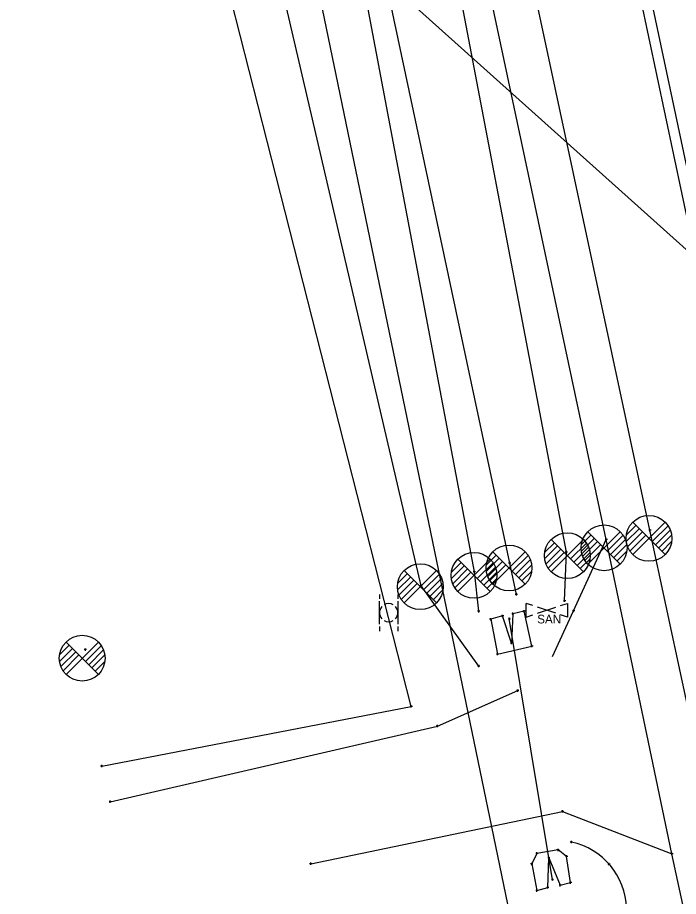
# Model space of a CAD drawing. Extents: x 1954856 to 2011933, y 399149 to 426294.
# Drawn here: x 2005971.8 to 2006043.9, y 402947.5 to 403043.4 of the extents above; entities that cross this region are included whole.
import ezdxf

# ---------------------------------------------------------------- set-up
doc = ezdxf.new("R2010")
doc.units = 0
for name, color, linetype in [('BankMent_ep', 7, 'Continuous'), ('BaselineSurvey', 7, 'Continuous'), ('DelineatorPost_ep', 7, 'Continuous'), ('Driveway_ep', 7, 'Continuous'), ('ElecAer_ep', 7, 'Continuous'), ('EndTreatMES_ep', 7, 'Continuous'), ('FlowLineInvert_ep', 7, 'Continuous'), ('PavtAsphalt_ep', 7, 'Continuous'), ('PavtAsphaltCrown_ep', 7, 'Continuous'), ('PipeCulvert_ep', 7, 'Continuous'), ('PointLocator_ep', 7, 'Continuous'), ('ShldrPaved_ep', 7, 'Continuous'), ('TreeLineWoods_ep', 7, 'Continuous'), ('ValveSewer_ep', 7, 'Continuous'), ('XSPt_ep', 7, 'Continuous')]:
    doc.layers.add(name, color=color, linetype=linetype)

msp = doc.modelspace()

# ---------------------------------------------------------------- linework, layer by layer
at = {"layer": 'BankMent_ep'}
for p, q in [((2006031.644, 402985.086), (2006013.054, 403082.745)), ((2006015.787, 402981.415), (2005993.355, 403077.812)), ((2006031.445, 402979.774), (2006031.644, 402985.086)), ((2006022.071, 402972.641), (2006015.787, 402981.415))]:
    msp.add_line(p, q, dxfattribs=at)
for points in [[(2006026.182, 402980.462), (2006025.451, 402983.887), (2006004.796, 403080.94), (2005986.553, 403176.869), (2005964.789, 403276.966), (2005944.375, 403374.63), (2005923.277, 403472.991), (2005901.17, 403570.474), (2005889.775, 403641.659)], [(2006022.07, 402978.635), (2006021.603, 402982.934), (2006003.186, 403080.575), (2005983.54, 403176.275), (2005962.468, 403276.293), (2005940.441, 403373.603), (2005921.465, 403472.813), (2005899.513, 403569.733), (2005886.484, 403640.977)]]:
    msp.add_lwpolyline(points, dxfattribs=at)
msp.add_arc((2006030.56, 402945.974), 7.645, 1.8807, 77.76145, dxfattribs=at)
at = {"layer": 'BaselineSurvey'}
msp.add_line((2006223.925, 402174.382), (2005094.479, 407516.047), dxfattribs=at)
msp.add_line((2006223.925, 402174.382), (2005094.479, 407516.047), dxfattribs=at)
at = {"layer": 'DelineatorPost_ep'}
for p, q in [((2006011.243, 402980.474), (2006011.243, 402979.974)), ((2006011.243, 402977.224), (2006011.243, 402979.724)), ((2006013.243, 402980.474), (2006013.243, 402979.974)), ((2006013.243, 402979.724), (2006013.243, 402977.224)), ((2006012.243, 402978.474), (2006012.243, 402978.474)), ((2006011.243, 402976.974), (2006011.243, 402976.474)), ((2006013.243, 402976.974), (2006013.243, 402976.474))]:
    msp.add_line(p, q, dxfattribs=at)
for start, end in [(138.59038, 221.40962), (60, 120), (318.59038, 41.40962), (240, 300)]:
    msp.add_arc((2006012.243, 402978.474), 1, start, end, dxfattribs=at)
at = {"layer": 'Driveway_ep'}
for p, q in [((2006032.413, 402978.669), (2006035.99, 402986.452)), ((2006030.134, 402973.71), (2006032.413, 402978.669)), ((2006017.562, 402966.093), (2006026.332, 402969.965)), ((2005981.873, 402957.848), (2006017.562, 402966.093)), ((2006003.74, 402951.077), (2006031.217, 402956.789)), ((2006031.217, 402956.789), (2006043.151, 402952.168))]:
    msp.add_line(p, q, dxfattribs=at)
at = {"layer": 'ElecAer_ep'}
msp.add_lwpolyline([(2006062.406, 402767.04), (2006002.661, 403055.822), (2006083.898, 402982.967)], dxfattribs=at)
at = {"layer": 'EndTreatMES_ep'}
for points in [[(2006023.384, 402977.75), (2006024.136, 402973.955), (2006027.869, 402974.829), (2006027.017, 402978.629), (2006025.793, 402978.353), (2006025.649, 402975.151), (2006024.679, 402978.115)], [(2006032.09, 402949.017), (2006031.659, 402951.872), (2006030.733, 402952.588), (2006028.412, 402952.204), (2006027.849, 402951.057), (2006028.409, 402948.141), (2006029.611, 402948.486), (2006029.717, 402951.726), (2006030.954, 402948.729)]]:
    msp.add_lwpolyline(points, close=True, dxfattribs=at)
at = {"layer": 'FlowLineInvert_ep'}
for p, q in [((2006025.494, 402977.744), (2006025.318, 402977.92)), ((2006025.494, 402977.92), (2006025.318, 402977.744)), ((2006025.406, 402977.832), (2006025.406, 402977.832)), ((2006030.209, 402949.239), (2006030.033, 402949.415)), ((2006030.209, 402949.415), (2006030.033, 402949.239)), ((2006030.121, 402949.327), (2006030.121, 402949.327))]:
    msp.add_line(p, q, dxfattribs=at)
at = {"layer": 'PavtAsphalt_ep'}
for p, q in [((2006040.75, 402987.463), (2006019.985, 403084.459)), ((2006061.812, 402888.943), (2006040.75, 402987.463))]:
    msp.add_line(p, q, dxfattribs=at)
at = {"layer": 'PavtAsphaltCrown_ep'}
msp.add_lwpolyline([(2006221.576, 402197.041), (2006219.373, 402206.688), (2006198.419, 402304.427), (2006177.674, 402402.212), (2006156.488, 402500.143), (2006135.917, 402597.882), (2006115.394, 402695.489), (2006094.3, 402793.442), (2006073.801, 402891.433), (2006052.859, 402989.16), (2006032.075, 403086.962), (2006011.062, 403184.663), (2005990.583, 403282.628), (2005969.857, 403380.234), (2005949.302, 403478.326), (2005928.678, 403576.103), (2005908.104, 403674.029), (2005887.142, 403771.84)], dxfattribs=at)
at = {"layer": 'PipeCulvert_ep'}
msp.add_lwpolyline([(2006030.121, 402949.327), (2006025.406, 402977.832)], dxfattribs=at)
at = {"layer": 'PointLocator_ep'}
for p, q in [((2006040.875, 402987.463), (2006040.625, 402987.463)), ((2006040.75, 402987.338), (2006040.75, 402987.588)), ((2006040.75, 402987.463), (2006040.75, 402987.463)), ((2006036.115, 402986.452), (2006035.865, 402986.452)), ((2006035.99, 402986.327), (2006035.99, 402986.577)), ((2006035.99, 402986.452), (2006035.99, 402986.452)), ((2006031.769, 402985.086), (2006031.519, 402985.086)), ((2006031.644, 402984.961), (2006031.644, 402985.211)), ((2006031.644, 402985.086), (2006031.644, 402985.086)), ((2006025.576, 402983.887), (2006025.326, 402983.887)), ((2006025.451, 402983.762), (2006025.451, 402984.012)), ((2006025.451, 402983.887), (2006025.451, 402983.887)), ((2006021.728, 402982.934), (2006021.478, 402982.934)), ((2006021.603, 402982.809), (2006021.603, 402983.059)), ((2006021.603, 402982.934), (2006021.603, 402982.934)), ((2006015.787, 402981.29), (2006015.787, 402981.54)), ((2006015.912, 402981.415), (2006015.662, 402981.415)), ((2006015.787, 402981.415), (2006015.787, 402981.415)), ((2006026.182, 402980.337), (2006026.182, 402980.587)), ((2006026.307, 402980.462), (2006026.057, 402980.462)), ((2006026.182, 402980.462), (2006026.182, 402980.462)), ((2006031.57, 402979.774), (2006031.32, 402979.774)), ((2006031.445, 402979.649), (2006031.445, 402979.899)), ((2006031.445, 402979.774), (2006031.445, 402979.774)), ((2006022.07, 402978.51), (2006022.07, 402978.76)), ((2006027.017, 402978.504), (2006027.017, 402978.754)), ((2006032.538, 402978.669), (2006032.288, 402978.669)), ((2006032.413, 402978.544), (2006032.413, 402978.794)), ((2006032.413, 402978.669), (2006032.413, 402978.669)), ((2006022.195, 402978.635), (2006021.945, 402978.635)), ((2006022.07, 402978.635), (2006022.07, 402978.635)), ((2006023.509, 402977.75), (2006023.259, 402977.75)), ((2006023.384, 402977.625), (2006023.384, 402977.875)), ((2006023.384, 402977.75), (2006023.384, 402977.75)), ((2006024.804, 402978.115), (2006024.554, 402978.115)), ((2006024.679, 402977.99), (2006024.679, 402978.24)), ((2006024.679, 402978.115), (2006024.679, 402978.115)), ((2006025.918, 402978.353), (2006025.668, 402978.353)), ((2006025.793, 402978.228), (2006025.793, 402978.478)), ((2006025.793, 402978.353), (2006025.793, 402978.353)), ((2006027.142, 402978.629), (2006026.892, 402978.629)), ((2006027.017, 402978.629), (2006027.017, 402978.629)), ((2006025.774, 402975.151), (2006025.524, 402975.151)), ((2006025.649, 402975.026), (2006025.649, 402975.276)), ((2006025.649, 402975.151), (2006025.649, 402975.151)), ((2006027.994, 402974.829), (2006027.744, 402974.829)), ((2006027.869, 402974.704), (2006027.869, 402974.954)), ((2006027.869, 402974.829), (2006027.869, 402974.829)), ((2005979.279, 402974.448), (2005979.029, 402974.448)), ((2005979.154, 402974.323), (2005979.154, 402974.573)), ((2005979.154, 402974.448), (2005979.154, 402974.448)), ((2006024.261, 402973.955), (2006024.011, 402973.955)), ((2006024.136, 402973.83), (2006024.136, 402974.08)), ((2006024.136, 402973.955), (2006024.136, 402973.955)), ((2006022.196, 402972.641), (2006021.946, 402972.641)), ((2006022.071, 402972.516), (2006022.071, 402972.766)), ((2006022.071, 402972.641), (2006022.071, 402972.641)), ((2006026.332, 402969.84), (2006026.332, 402970.09)), ((2006026.457, 402969.965), (2006026.207, 402969.965)), ((2006026.332, 402969.965), (2006026.332, 402969.965)), ((2006014.835, 402968.248), (2006014.585, 402968.248)), ((2006014.71, 402968.123), (2006014.71, 402968.373)), ((2006014.71, 402968.248), (2006014.71, 402968.248)), ((2006017.562, 402965.968), (2006017.562, 402966.218)), ((2006017.687, 402966.093), (2006017.437, 402966.093)), ((2006017.562, 402966.093), (2006017.562, 402966.093)), ((2005981.059, 402961.73), (2005980.809, 402961.73)), ((2005980.934, 402961.605), (2005980.934, 402961.855)), ((2005980.934, 402961.73), (2005980.934, 402961.73)), ((2005981.998, 402957.848), (2005981.748, 402957.848)), ((2005981.873, 402957.723), (2005981.873, 402957.973)), ((2005981.873, 402957.848), (2005981.873, 402957.848)), ((2006031.342, 402956.789), (2006031.092, 402956.789)), ((2006031.217, 402956.664), (2006031.217, 402956.914)), ((2006031.217, 402956.789), (2006031.217, 402956.789)), ((2006032.306, 402953.445), (2006032.056, 402953.445)), ((2006032.181, 402953.32), (2006032.181, 402953.57)), ((2006032.181, 402953.445), (2006032.181, 402953.445)), ((2006028.537, 402952.204), (2006028.287, 402952.204)), ((2006028.412, 402952.079), (2006028.412, 402952.329)), ((2006028.412, 402952.204), (2006028.412, 402952.204)), ((2006029.717, 402951.601), (2006029.717, 402951.851)), ((2006030.858, 402952.588), (2006030.608, 402952.588)), ((2006030.733, 402952.463), (2006030.733, 402952.713)), ((2006030.733, 402952.588), (2006030.733, 402952.588)), ((2006031.784, 402951.872), (2006031.534, 402951.872)), ((2006031.659, 402951.747), (2006031.659, 402951.997)), ((2006031.659, 402951.872), (2006031.659, 402951.872)), ((2006043.276, 402952.168), (2006043.026, 402952.168)), ((2006043.151, 402952.043), (2006043.151, 402952.293)), ((2006043.151, 402952.168), (2006043.151, 402952.168)), ((2006003.865, 402951.077), (2006003.615, 402951.077)), ((2006003.74, 402950.952), (2006003.74, 402951.202)), ((2006003.74, 402951.077), (2006003.74, 402951.077)), ((2006027.974, 402951.057), (2006027.724, 402951.057)), ((2006027.849, 402950.932), (2006027.849, 402951.182)), ((2006027.849, 402951.057), (2006027.849, 402951.057)), ((2006029.842, 402951.726), (2006029.592, 402951.726)), ((2006029.717, 402951.726), (2006029.717, 402951.726)), ((2006036.408, 402951.043), (2006036.158, 402951.043)), ((2006036.283, 402950.918), (2006036.283, 402951.168)), ((2006036.283, 402951.043), (2006036.283, 402951.043)), ((2006032.215, 402949.017), (2006031.965, 402949.017)), ((2006032.09, 402948.892), (2006032.09, 402949.142)), ((2006032.09, 402949.017), (2006032.09, 402949.017)), ((2006028.534, 402948.141), (2006028.284, 402948.141)), ((2006028.409, 402948.016), (2006028.409, 402948.266)), ((2006028.409, 402948.141), (2006028.409, 402948.141)), ((2006029.736, 402948.486), (2006029.486, 402948.486)), ((2006029.611, 402948.361), (2006029.611, 402948.611)), ((2006029.611, 402948.486), (2006029.611, 402948.486)), ((2006031.079, 402948.729), (2006030.829, 402948.729)), ((2006030.954, 402948.604), (2006030.954, 402948.854)), ((2006030.954, 402948.729), (2006030.954, 402948.729))]:
    msp.add_line(p, q, dxfattribs=at)
at = {"layer": 'ShldrPaved_ep'}
for p, q in [((2006035.99, 402986.452), (2006015.245, 403083.769)), ((2006043.151, 402952.168), (2006035.99, 402986.452)), ((2006057.174, 402887.717), (2006043.151, 402952.168))]:
    msp.add_line(p, q, dxfattribs=at)
at = {"layer": 'TreeLineWoods_ep'}
msp.add_lwpolyline([(2005980.934, 402961.73), (2006014.71, 402968.248), (2005987.203, 403076.245), (2005968.268, 403172.205), (2005947.454, 403273.053), (2005926.011, 403370.82), (2005905.04, 403469.001), (2005886.708, 403566.956), (2005868.55, 403644.14), (2005837.958, 403637.86)], dxfattribs=at)
at = {"layer": 'ValveSewer_ep'}
for p, q in [((2006027.99, 402979.244), (2006027.24, 402979.494)), ((2006027.24, 402977.994), (2006027.24, 402979.494)), ((2006030.49, 402978.411), (2006028.49, 402979.077)), ((2006028.49, 402978.411), (2006030.49, 402979.077)), ((2006029.49, 402978.744), (2006029.49, 402978.744)), ((2006030.99, 402979.244), (2006031.74, 402979.494)), ((2006031.74, 402979.494), (2006031.74, 402977.994)), ((2006027.24, 402977.994), (2006027.99, 402978.244)), ((2006031.74, 402977.994), (2006030.99, 402978.244))]:
    msp.add_line(p, q, dxfattribs=at)
at = {"layer": 'XSPt_ep'}
for p, q in [((2006038.871, 402984.813), (2006042.407, 402988.349)), ((2006042.407, 402984.813), (2006038.871, 402988.349)), ((2006033.98, 402983.779), (2006037.516, 402987.315)), ((2006037.516, 402983.779), (2006033.98, 402987.315)), ((2006038.164, 402986.935), (2006039.225, 402987.995)), ((2006038.164, 402986.227), (2006039.578, 402987.642)), ((2006038.312, 402985.668), (2006039.932, 402987.288)), ((2006040.993, 402986.227), (2006042.725, 402987.959)), ((2006041.346, 402985.874), (2006042.966, 402987.494)), ((2006029.968, 402982.93), (2006033.504, 402986.466)), ((2006033.504, 402982.93), (2006029.968, 402986.466)), ((2006033.273, 402985.901), (2006034.334, 402986.961)), ((2006033.273, 402985.193), (2006034.687, 402986.608)), ((2006036.102, 402985.193), (2006037.834, 402986.925)), ((2006036.455, 402984.84), (2006038.075, 402986.46)), ((2006038.553, 402985.203), (2006040.285, 402986.935)), ((2006040.639, 402986.581), (2006040.639, 402986.581)), ((2006041.7, 402985.52), (2006043.114, 402986.935)), ((2006029.261, 402985.052), (2006030.322, 402986.112)), ((2006029.261, 402984.344), (2006030.675, 402985.759)), ((2006029.409, 402983.785), (2006031.029, 402985.405)), ((2006032.09, 402984.344), (2006033.822, 402986.076)), ((2006032.443, 402983.991), (2006034.063, 402985.611)), ((2006033.421, 402984.634), (2006035.041, 402986.254)), ((2006033.662, 402984.169), (2006035.394, 402985.901)), ((2006035.748, 402985.547), (2006035.748, 402985.547)), ((2006036.809, 402984.486), (2006038.223, 402985.901)), ((2006042.053, 402985.167), (2006043.114, 402986.227)), ((2006022.902, 402983.708), (2006023.963, 402984.768)), ((2006022.902, 402983), (2006024.316, 402984.415)), ((2006023.609, 402981.586), (2006027.145, 402985.122)), ((2006027.145, 402981.586), (2006023.609, 402985.122)), ((2006025.731, 402983), (2006027.463, 402984.732)), ((2006029.65, 402983.32), (2006031.382, 402985.052)), ((2006031.736, 402984.698), (2006031.736, 402984.698)), ((2006032.797, 402983.637), (2006034.211, 402985.052)), ((2006037.162, 402984.133), (2006038.223, 402985.193)), ((2006019.086, 402982.901), (2006020.147, 402983.961)), ((2006019.086, 402982.193), (2006020.5, 402983.608)), ((2006019.793, 402980.779), (2006023.329, 402984.315)), ((2006023.329, 402980.779), (2006019.793, 402984.315)), ((2006021.915, 402982.193), (2006023.647, 402983.925)), ((2006022.268, 402981.84), (2006023.888, 402983.46)), ((2006023.05, 402982.441), (2006024.67, 402984.061)), ((2006023.291, 402981.976), (2006025.023, 402983.708)), ((2006026.084, 402982.647), (2006027.704, 402984.267)), ((2006026.438, 402982.293), (2006027.852, 402983.708)), ((2006033.15, 402983.284), (2006034.211, 402984.344)), ((2006013.216, 402981.66), (2006014.277, 402982.72)), ((2006013.923, 402979.538), (2006017.459, 402983.074)), ((2006017.459, 402979.538), (2006013.923, 402983.074)), ((2006016.045, 402980.952), (2006017.777, 402982.684)), ((2006019.234, 402981.634), (2006020.854, 402983.254)), ((2006019.475, 402981.169), (2006021.207, 402982.901)), ((2006021.561, 402982.547), (2006021.561, 402982.547)), ((2006022.622, 402981.486), (2006024.036, 402982.901)), ((2006025.377, 402983.354), (2006025.377, 402983.354)), ((2006026.791, 402981.94), (2006027.852, 402983)), ((2006013.216, 402980.952), (2006014.63, 402982.367)), ((2006013.364, 402980.393), (2006014.984, 402982.013)), ((2006013.605, 402979.928), (2006015.337, 402981.66)), ((2006016.398, 402980.599), (2006018.018, 402982.219)), ((2006016.752, 402980.245), (2006018.166, 402981.66)), ((2006022.975, 402981.133), (2006024.036, 402982.193)), ((2006015.691, 402981.306), (2006015.691, 402981.306)), ((2006017.105, 402979.892), (2006018.166, 402980.952)), ((2005976.332, 402973.861), (2005977.393, 402974.921)), ((2005977.039, 402971.739), (2005980.575, 402975.275)), ((2005980.575, 402971.739), (2005977.039, 402975.275)), ((2005979.161, 402973.153), (2005980.893, 402974.885)), ((2005976.332, 402973.153), (2005977.746, 402974.568)), ((2005976.48, 402972.594), (2005978.1, 402974.214)), ((2005976.721, 402972.129), (2005978.453, 402973.861)), ((2005979.514, 402972.8), (2005981.134, 402974.42)), ((2005979.868, 402972.446), (2005981.282, 402973.861)), ((2005978.807, 402973.507), (2005978.807, 402973.507)), ((2005980.221, 402972.093), (2005981.282, 402973.153))]:
    msp.add_line(p, q, dxfattribs=at)
for centre in [(2006040.639, 402986.581), (2006035.748, 402985.547), (2006031.736, 402984.698), (2006025.377, 402983.354), (2006021.561, 402982.547), (2006015.691, 402981.306), (2005978.807, 402973.507)]:
    msp.add_circle(centre, 2.5, dxfattribs=at)

# ---------------------------------------------------------------- texts
at = {"layer": 'ValveSewer_ep'}
msp.add_text('SAN', height=0.95, dxfattribs=at).set_placement((2006028.451, 402977.302))

doc.saveas('drawing.dxf')
